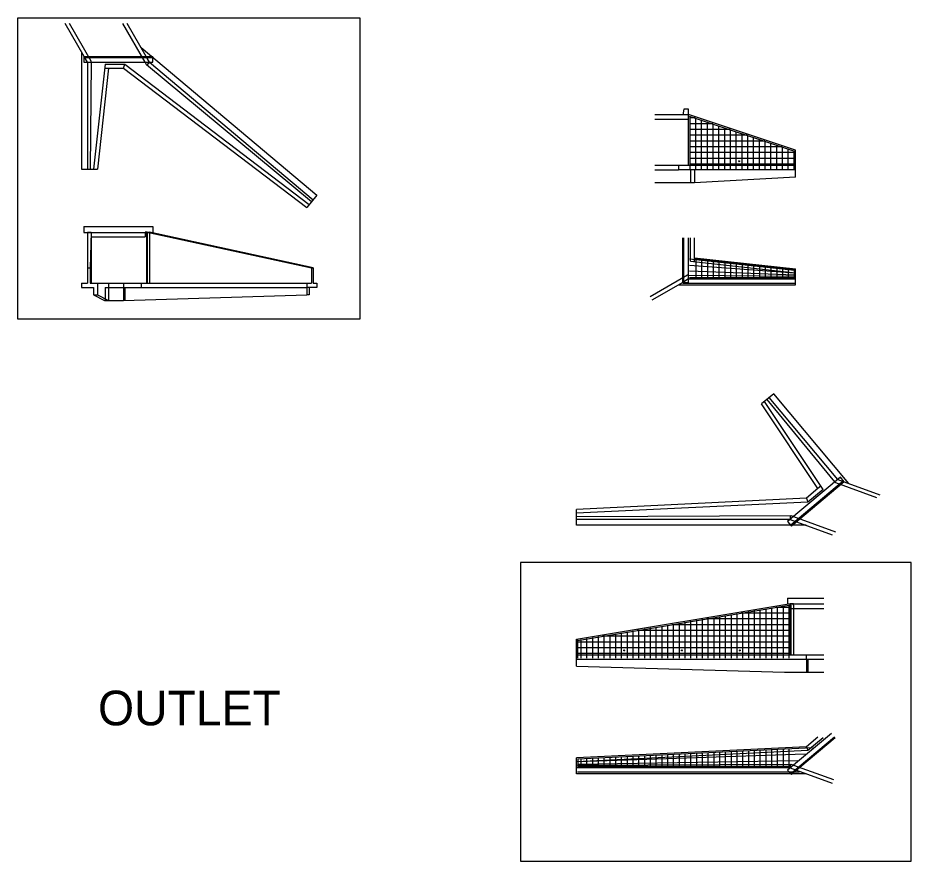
# Model space of a CAD drawing. Extents: x -21 to 491, y -228 to 155.
# Drawn here: x 14.1 to 168.7, y -198.6 to -52.7 of the extents above; entities that cross this region are included whole.
import ezdxf

# ---------------------------------------------------------------- set-up
doc = ezdxf.new("R2010")
doc.units = 0
for name, color, linetype in [('1', 7, 'Continuous'), ('4', 7, 'Continuous'), ('B-Gen-Construction', 7, 'Continuous'), ('B-Gen-Hidden', 7, 'Continuous'), ('B-Gen-Object', 7, 'Continuous'), ('B-Gen-Rebar', 7, 'Continuous')]:
    doc.layers.add(name, color=color, linetype=linetype)

msp = doc.modelspace()

# ---------------------------------------------------------------- linework, layer by layer
at = {"layer": '4'}
for points in [[(14.08, -52.69), (73.28, -52.69), (73.28, -104.81), (14.08, -104.81)], [(101.13, -198.59), (168.74, -198.59), (168.74, -146.93), (101.13, -146.93)]]:
    msp.add_lwpolyline(points, close=True, dxfattribs=at)
at = {"layer": 'B-Gen-Construction'}
msp.add_line((131.19, -94.37), (148.69, -96.29), dxfattribs=at)
at = {"layer": 'B-Gen-Hidden'}
for p, q in [((26.77, -60.19), (23.02, -53.69)), ((36.11, -60.37), (32.26, -53.69)), ((26.11, -60.37), (25.53, -59.37)), ((26.77, -60.37), (26.77, -60.19)), ((36.88, -60.37), (36.31, -59.37)), ((29.18, -60.7), (27.19, -78.87)), ((29.1, -61.37), (29.77, -61.37)), ((29.18, -60.7), (32.6, -60.7)), ((32.37, -61.37), (32.6, -60.7)), ((32.6, -60.7), (64.53, -84.98)), ((130.21, -70.26), (124.39, -70.26)), ((128.48, -78.26), (124.39, -78.26)), ((131.21, -79.01), (131.21, -81.26)), ((26.11, -89.8), (37.08, -89.8)), ((36.88, -89.76), (36.88, -98.59)), ((130.54, -94.8), (130.54, -90.77)), ((131.21, -94.87), (131.21, -94.2)), ((130.54, -94.8), (148.71, -96.79)), ((130.03, -97.2), (123.53, -100.96)), ((130.21, -97.2), (130.03, -97.2)), ((35.42, -98.59), (35.42, -99.34)), ((130.21, -97.87), (129.21, -98.45)), ((29.18, -99.34), (64.1, -99.34)), ((29.18, -99.34), (29.18, -101.59)), ((32.6, -99.34), (32.6, -101.58)), ((153.5, -134.27), (143.34, -119.07)), ((155.55, -132.98), (155.67, -133.11)), ((156.06, -132.55), (157.15, -132.94)), ((153.5, -134.27), (150.88, -136.46)), ((153.13, -133.71), (152.61, -134.14)), ((155.67, -133.11), (162.72, -135.68)), ((150.62, -135.81), (150.88, -136.46)), ((150.88, -136.46), (110.81, -138.39)), ((148.4, -138.98), (155.65, -141.62)), ((147.81, -139.48), (148.89, -139.87)), ((147.56, -154.08), (147.81, -154.04)), ((147.81, -154.08), (147.81, -154.04)), ((147.81, -154.04), (148.4, -154.04)), ((147.92, -154.29), (147.92, -154.04)), ((147.92, -154.29), (147.92, -162.88)), ((148.4, -154.29), (148.4, -154.04)), ((148.4, -154.29), (148.4, -162.88)), ((147.8, -154.88), (153.62, -154.88)), ((150.55, -162.88), (153.62, -162.88)), ((150.62, -163.67), (150.62, -165.88)), ((153.5, -177.27), (150.88, -179.47)), ((150.62, -178.82), (150.88, -179.47)), ((150.88, -179.47), (110.81, -181.4)), ((147.81, -182.48), (148.89, -182.88)), ((148.4, -181.99), (155.28, -184.49))]:
    msp.add_line(p, q, dxfattribs=at)
at = {"layer": 'B-Gen-Object'}
for p, q in [((25.53, -59.37), (22.25, -53.69)), ((36.31, -59.37), (33.03, -53.69)), ((25.11, -58.64), (25.11, -78.87)), ((35.42, -57.84), (65.87, -83.39)), ((25.52, -59.37), (25.52, -60.37)), ((25.52, -59.37), (37.47, -59.37)), ((25.53, -59.54), (37.47, -59.54)), ((37.47, -60.37), (37.47, -59.37)), ((25.52, -60.37), (37.47, -60.37)), ((26.11, -60.37), (26.11, -78.87)), ((26.77, -60.37), (26.61, -78.87)), ((29.77, -61.37), (27.86, -78.87)), ((29.77, -61.37), (32.37, -61.37)), ((32.37, -61.37), (64.1, -85.49)), ((36.37, -60.81), (36.11, -60.37)), ((64.91, -84.54), (36.37, -60.81)), ((36.46, -60.88), (36.88, -60.37)), ((36.88, -60.37), (65.23, -84.15)), ((130.21, -69.47), (124.39, -69.47)), ((129.37, -68.47), (129.2, -69.47)), ((130.21, -68.47), (129.37, -68.47)), ((130.21, -78.26), (130.21, -68.47)), ((148.71, -75.6), (130.21, -69.43)), ((148.71, -80.26), (148.71, -75.6)), ((25.11, -78.87), (27.86, -78.87)), ((148.71, -78.26), (128.48, -78.26)), ((128.48, -78.26), (128.48, -79.06)), ((128.48, -79.06), (124.39, -79.06)), ((148.71, -79.01), (128.48, -79.01)), ((128.48, -79.01), (128.48, -79.01)), ((130.54, -79.01), (130.54, -81.26)), ((148.71, -80.26), (131.21, -81.26)), ((131.21, -81.26), (124.39, -81.26)), ((65.87, -83.39), (64.1, -85.49)), ((25.52, -88.8), (37.47, -88.8)), ((25.52, -88.8), (25.52, -89.8)), ((37.47, -88.8), (37.47, -89.8)), ((25.52, -89.8), (26.11, -89.8)), ((26.11, -89.76), (26.11, -98.59)), ((26.11, -89.76), (26.77, -89.76)), ((26.77, -89.76), (26.61, -95.92)), ((26.77, -89.76), (26.77, -98.59)), ((26.77, -90.59), (36.11, -90.59)), ((36.11, -89.76), (36.11, -90.59)), ((36.46, -89.76), (36.11, -89.76)), ((36.37, -89.76), (36.37, -98.59)), ((36.46, -89.76), (36.88, -89.76)), ((36.46, -89.76), (64.91, -95.92)), ((36.46, -89.76), (36.46, -98.59)), ((65.23, -95.92), (36.88, -89.76)), ((37.08, -89.8), (37.47, -89.8)), ((129.21, -98.45), (129.21, -90.77)), ((129.37, -98.45), (129.37, -90.77)), ((130.21, -98.45), (130.21, -90.77)), ((131.21, -94.2), (131.21, -90.77)), ((131.21, -94.2), (148.71, -96.12)), ((26.11, -95.92), (26.61, -95.92)), ((26.61, -95.92), (26.61, -98.59)), ((64.91, -95.92), (64.91, -98.59)), ((64.91, -95.92), (65.23, -95.92)), ((65.23, -95.92), (65.23, -98.59)), ((130.21, -97.2), (148.71, -97.37)), ((148.71, -98.87), (148.71, -96.12)), ((25.11, -98.59), (25.11, -99.34)), ((25.11, -98.59), (26.11, -98.59)), ((26.61, -98.59), (64.91, -98.59)), ((27.86, -98.59), (27.86, -100.59)), ((29.77, -98.59), (29.77, -101.59)), ((32.37, -98.59), (32.37, -101.59)), ((64.1, -98.59), (64.1, -100.59)), ((65.23, -98.59), (65.87, -98.59)), ((65.87, -98.59), (65.87, -99.34)), ((129.21, -98.45), (123.86, -101.53)), ((128.48, -98.87), (148.71, -98.87)), ((129.21, -98.45), (130.21, -98.45)), ((130.21, -97.87), (148.71, -97.87)), ((25.11, -99.34), (27.19, -99.34)), ((27.19, -99.34), (27.19, -100.59)), ((65.87, -99.34), (64.1, -99.34)), ((64.53, -99.34), (64.53, -100.59)), ((27.19, -100.59), (27.86, -100.59)), ((27.19, -100.59), (29.1, -101.59)), ((27.86, -100.59), (29.77, -101.59)), ((29.1, -101.59), (32.37, -101.59)), ((32.37, -101.59), (64.1, -100.59)), ((64.53, -100.59), (64.1, -100.59)), ((144.94, -117.73), (142.83, -119.5)), ((155.55, -132.98), (143.79, -118.7)), ((156.06, -132.55), (144.17, -118.38)), ((157.94, -133.23), (144.94, -117.73)), ((152.61, -134.14), (142.83, -119.5)), ((156.51, -132.17), (147.36, -139.85)), ((157.04, -132.82), (147.9, -140.49)), ((157.15, -132.94), (148, -140.62)), ((157.15, -132.94), (156.51, -132.17)), ((157.15, -132.94), (163.31, -135.19)), ((152.61, -134.14), (150.62, -135.81)), ((150.62, -135.81), (110.81, -137.73)), ((110.81, -140.48), (110.81, -137.73)), ((110.81, -138.98), (147.92, -138.81)), ((147.81, -138.81), (147.81, -139.48)), ((147.92, -138.81), (148.4, -138.98)), ((147.81, -139.48), (110.81, -139.48)), ((150.55, -140.48), (110.81, -140.48)), ((147.36, -139.85), (148, -140.62)), ((148.89, -139.87), (155.06, -142.11)), ((147.36, -153.08), (153.62, -153.08)), ((147.36, -153.08), (147.36, -154.08)), ((110.81, -160.21), (147.56, -154.08)), ((147.36, -154.08), (153.62, -154.08)), ((147.81, -154.08), (147.81, -162.88)), ((110.81, -164.88), (110.81, -160.21)), ((110.81, -162.88), (150.55, -162.88)), ((110.81, -163.63), (150.55, -163.63)), ((150.55, -162.88), (150.55, -163.67)), ((150.55, -163.63), (150.55, -163.63)), ((150.55, -163.67), (153.62, -163.67)), ((150.88, -163.67), (150.88, -165.88)), ((110.81, -164.88), (146.8, -165.88)), ((146.8, -165.88), (153.62, -165.88)), ((154.95, -176.49), (147.36, -182.86)), ((155.48, -177.13), (147.9, -183.5)), ((155.59, -177.26), (148, -183.62)), ((152.61, -177.15), (150.62, -178.82)), ((150.62, -178.82), (110.81, -180.73)), ((110.81, -183.48), (110.81, -180.73)), ((110.81, -181.98), (147.92, -181.82)), ((147.81, -182.48), (110.81, -182.48)), ((147.81, -181.82), (147.81, -182.48)), ((147.92, -181.82), (148.4, -181.99)), ((150.55, -183.48), (110.81, -183.48)), ((147.36, -182.86), (148, -183.62)), ((148.89, -182.88), (155.06, -185.12))]:
    msp.add_line(p, q, dxfattribs=at)
for centre in [(138.96, -77.51), (119.06, -162.13), (129.06, -162.13), (139.06, -162.13)]:
    msp.add_circle(centre, 0.0833, dxfattribs=at)
at = {"layer": 'B-Gen-Rebar'}
for p, q in [((148.63, -75.84), (130.37, -69.75)), ((131.43, -70.01), (130.37, -70.01)), ((134.43, -71.01), (130.37, -71.01)), ((130.46, -78.85), (130.46, -69.69)), ((131.46, -78.85), (131.46, -70.02)), ((132.46, -78.85), (132.46, -70.36)), ((133.46, -78.85), (133.46, -70.69)), ((134.46, -78.85), (134.46, -71.02)), ((137.43, -72.01), (130.37, -72.01)), ((135.46, -78.85), (135.46, -71.36)), ((136.46, -78.85), (136.46, -71.69)), ((137.46, -78.85), (137.46, -72.02)), ((138.46, -78.85), (138.46, -72.36)), ((139.46, -78.85), (139.46, -72.69)), ((140.43, -73.01), (130.37, -73.01)), ((143.43, -74.01), (130.37, -74.01)), ((140.46, -78.85), (140.46, -73.02)), ((141.46, -78.85), (141.46, -73.36)), ((142.46, -78.85), (142.46, -73.69)), ((143.46, -78.85), (143.46, -74.02)), ((146.43, -75.01), (130.37, -75.01)), ((144.46, -78.85), (144.46, -74.36)), ((145.46, -78.85), (145.46, -74.69)), ((146.46, -78.85), (146.46, -75.02)), ((147.46, -78.85), (147.46, -75.36)), ((148.46, -78.85), (148.46, -75.69)), ((148.54, -76.01), (130.37, -76.01)), ((148.54, -77.01), (130.37, -77.01)), ((148.54, -78.01), (130.37, -78.01)), ((130.37, -94.36), (148.54, -96.35)), ((130.37, -95.45), (148.54, -96.78)), ((131.46, -94.4), (131.46, -97.7)), ((132.46, -94.51), (132.46, -97.7)), ((133.46, -94.62), (133.46, -97.7)), ((134.46, -94.73), (134.46, -97.7)), ((135.46, -94.84), (135.46, -97.7)), ((136.46, -94.95), (136.46, -97.7)), ((137.46, -95.06), (137.46, -97.7)), ((138.46, -95.17), (138.46, -97.7)), ((139.46, -95.28), (139.46, -97.7)), ((140.46, -95.38), (140.46, -97.7)), ((141.46, -95.49), (141.46, -97.7)), ((142.46, -95.6), (142.46, -97.7)), ((143.46, -95.71), (143.46, -97.7)), ((144.46, -95.82), (144.46, -97.7)), ((148.54, -97.2), (130.37, -96.54)), ((145.46, -95.93), (145.46, -97.7)), ((146.46, -96.04), (146.46, -97.7)), ((147.46, -96.15), (147.46, -97.7)), ((148.46, -96.26), (148.46, -97.7)), ((129.21, -98.62), (148.54, -98.62)), ((130.37, -97.62), (148.54, -97.62)), ((110.97, -160.44), (147.64, -154.32)), ((145.32, -154.63), (147.64, -154.63)), ((145.56, -154.59), (145.56, -163.46)), ((146.56, -154.42), (146.56, -163.46)), ((147.56, -154.29), (147.56, -163.46)), ((136.56, -156.09), (136.56, -163.46)), ((137.56, -155.92), (137.56, -163.46)), ((138.56, -155.75), (138.56, -163.46)), ((139.32, -155.63), (147.64, -155.63)), ((139.56, -155.59), (139.56, -163.46)), ((140.56, -155.42), (140.56, -163.46)), ((141.56, -155.25), (141.56, -163.46)), ((142.56, -155.09), (142.56, -163.46)), ((143.56, -154.92), (143.56, -163.46)), ((144.56, -154.75), (144.56, -163.46)), ((126.56, -157.75), (126.56, -163.46)), ((127.32, -157.63), (147.64, -157.63)), ((127.56, -157.59), (127.56, -163.46)), ((128.56, -157.42), (128.56, -163.46)), ((129.56, -157.25), (129.56, -163.46)), ((130.56, -157.09), (130.56, -163.46)), ((131.56, -156.92), (131.56, -163.46)), ((132.56, -156.75), (132.56, -163.46)), ((133.32, -156.63), (147.64, -156.63)), ((133.56, -156.59), (133.56, -163.46)), ((134.56, -156.42), (134.56, -163.46)), ((135.56, -156.25), (135.56, -163.46)), ((117.56, -159.25), (117.56, -163.46)), ((118.56, -159.09), (118.56, -163.46)), ((119.56, -158.92), (119.56, -163.46)), ((120.56, -158.75), (120.56, -163.46)), ((121.32, -158.63), (147.64, -158.63)), ((121.56, -158.59), (121.56, -163.46)), ((122.56, -158.42), (122.56, -163.46)), ((123.56, -158.25), (123.56, -163.46)), ((124.56, -158.09), (124.56, -163.46)), ((125.56, -157.92), (125.56, -163.46)), ((110.97, -160.63), (147.64, -160.63)), ((111.06, -163.46), (111.06, -160.3)), ((111.56, -160.25), (111.56, -163.46)), ((112.56, -160.09), (112.56, -163.46)), ((113.56, -159.92), (113.56, -163.46)), ((114.56, -159.75), (114.56, -163.46)), ((115.32, -159.63), (147.64, -159.63)), ((115.56, -159.59), (115.56, -163.46)), ((116.56, -159.42), (116.56, -163.46)), ((110.97, -161.63), (147.64, -161.63)), ((110.97, -162.63), (147.64, -162.63)), ((151.68, -179.02), (110.97, -180.97)), ((142.56, -179.37), (142.56, -182.32)), ((143.56, -179.32), (143.56, -182.32)), ((144.56, -179.27), (144.56, -182.32)), ((145.56, -179.23), (145.56, -182.32)), ((146.56, -179.18), (146.56, -182.32)), ((147.56, -179.13), (147.56, -182.32)), ((150.4, -180.09), (110.97, -181.39)), ((111.06, -180.89), (111.06, -182.32)), ((111.56, -180.86), (111.56, -182.32)), ((112.56, -180.82), (112.56, -182.32)), ((113.56, -180.77), (113.56, -182.32)), ((114.56, -180.72), (114.56, -182.32)), ((115.56, -180.67), (115.56, -182.32)), ((116.56, -180.62), (116.56, -182.32)), ((117.56, -180.57), (117.56, -182.32)), ((118.56, -180.53), (118.56, -182.32)), ((119.56, -180.48), (119.56, -182.32)), ((120.56, -180.43), (120.56, -182.32)), ((121.56, -180.38), (121.56, -182.32)), ((122.56, -180.33), (122.56, -182.32)), ((123.56, -180.29), (123.56, -182.32)), ((124.56, -180.24), (124.56, -182.32)), ((125.56, -180.19), (125.56, -182.32)), ((126.56, -180.14), (126.56, -182.32)), ((127.56, -180.09), (127.56, -182.32)), ((128.56, -180.04), (128.56, -182.32)), ((129.56, -180), (129.56, -182.32)), ((130.56, -179.95), (130.56, -182.32)), ((131.56, -179.9), (131.56, -182.32)), ((132.56, -179.85), (132.56, -182.32)), ((133.56, -179.8), (133.56, -182.32)), ((134.56, -179.76), (134.56, -182.32)), ((135.56, -179.71), (135.56, -182.32)), ((136.56, -179.66), (136.56, -182.32)), ((137.56, -179.61), (137.56, -182.32)), ((138.56, -179.56), (138.56, -182.32)), ((139.56, -179.52), (139.56, -182.32)), ((140.56, -179.47), (140.56, -182.32)), ((141.56, -179.42), (141.56, -182.32)), ((110.97, -181.81), (149.12, -181.16)), ((147.85, -182.23), (110.97, -182.23)), ((149.43, -183.23), (110.97, -183.23))]:
    msp.add_line(p, q, dxfattribs=at)

# ---------------------------------------------------------------- texts
at = {"layer": '1'}
msp.add_text('OUTLET', height=6, dxfattribs=at).set_placement((27.96, -175.1))

doc.saveas('drawing.dxf')
